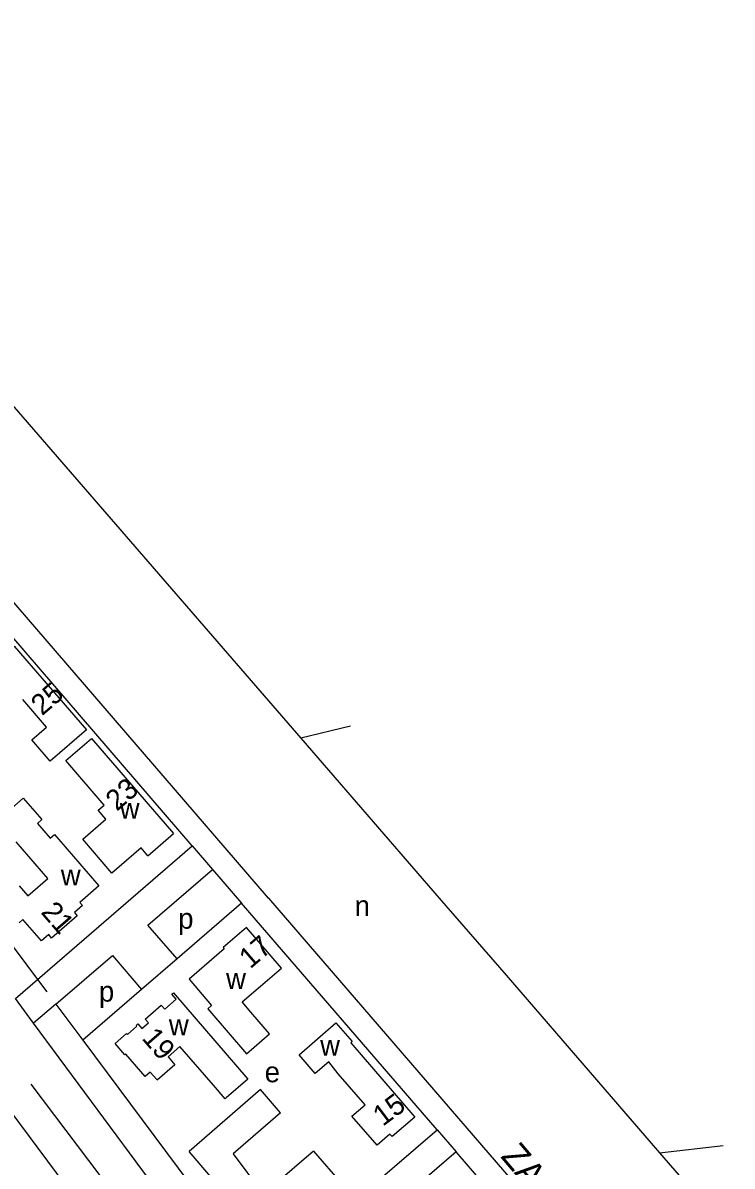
# Model space of a CAD drawing. Extents: x 155854 to 157362, y 383621 to 384685.
# Drawn here: x 156707.1 to 156844.9, y 384447.9 to 384670 of the extents above; entities that cross this region are included whole.
import ezdxf

# ---------------------------------------------------------------- set-up
doc = ezdxf.new("R2010")
doc.units = 0
for name, color, linetype in [('BLT_Basislijn', 7, 'Continuous'), ('BLT_Bebouwing', 7, 'Continuous'), ('BLT_Centroide', 7, 'Continuous'), ('BLT_Huisnummer', 7, 'Continuous'), ('BLT_Straatnaam', 7, 'Continuous'), ('BLT_Vlakafsluiter', 7, 'Continuous')]:
    doc.layers.add(name, color=color, linetype=linetype)

msp = doc.modelspace()

# ---------------------------------------------------------------- linework, layer by layer
at = {"layer": 'BLT_Basislijn'}
for p, q in [((156738.35, 384519.08), (156620.78, 384655.36)), ((156754.81, 384500), (156738.35, 384519.08)), ((156739.97, 384510.11), (156743.89, 384505.55)), ((156731.33, 384494.75), (156743.89, 384505.55)), ((156743.89, 384505.55), (156749.54, 384498.99)), ((156754.83, 384499.98), (156754.81, 384500)), ((156737.03, 384488.17), (156731.33, 384494.75)), ((156713.47, 384479.41), (156724.48, 384488.82)), ((156724.48, 384488.82), (156730.12, 384482.21)), ((156705.61, 384480.46), (156709.91, 384484.17)), ((156709.91, 384484.17), (156711.69, 384481.79)), ((156736.02, 384481.32), (156736.34, 384481.59)), ((156736.34, 384481.59), (156750.81, 384464.84)), ((156713.47, 384479.41), (156709.1, 384475.67)), ((156734.62, 384478.39), (156736.86, 384480.35)), ((156736.86, 384480.35), (156736.02, 384481.32)), ((156709.1, 384475.67), (156707.36, 384478.07)), ((156730.81, 384476.5), (156733.92, 384479.2)), ((156733.92, 384479.2), (156734.62, 384478.39)), ((156727.37, 384473.5), (156729.2, 384475.11)), ((156729.07, 384475.27), (156729.39, 384475.55)), ((156729.2, 384475.11), (156729.07, 384475.27)), ((156729.39, 384475.55), (156730.18, 384474.64)), ((156730.18, 384474.64), (156731.46, 384475.76)), ((156731.46, 384475.76), (156730.81, 384476.5)), ((156724.99, 384471.73), (156727.23, 384473.66)), ((156727.23, 384473.66), (156727.37, 384473.5)), ((156726.89, 384469.51), (156724.99, 384471.73)), ((156737.58, 384471.15), (156735.27, 384469.16)), ((156744.1, 384463.62), (156737.58, 384471.15)), ((156727.09, 384469.65), (156726.89, 384469.51)), ((156730.83, 384465.31), (156727.09, 384469.65)), ((156735.27, 384469.16), (156736.6, 384467.61)), ((156731.83, 384466.19), (156730.83, 384465.31)), ((156733.07, 384464.76), (156731.83, 384466.19)), ((156736.6, 384467.61), (156733.17, 384464.64)), ((156708.63, 384463.84), (156739.93, 384422.47)), ((156733.17, 384464.64), (156733.07, 384464.76)), ((156750.81, 384464.84), (156746.57, 384461.18)), ((156746.35, 384460.99), (156744.1, 384463.62)), ((156746.57, 384461.18), (156746.35, 384460.99)), ((156787.55, 384455), (156791.25, 384450.67))]:
    msp.add_line(p, q, dxfattribs=at)
for points in [[(156640.63, 384670.01), (156709.96, 384590.03), (156761.05, 384531.07)], [(156739.97, 384510.11), (156702.06, 384554.11)], [(156675.02, 384530.89), (156709.91, 384484.17)], [(156761.05, 384531.07), (156787.96, 384500)], [(156709.91, 384484.17), (156739.97, 384510.11)], [(156728.01, 384499.98), (156728.03, 384500)], [(156828.31, 384414.81), (156754.83, 384499.98)], [(156787.96, 384500), (156787.98, 384499.98)], [(156787.98, 384499.98), (156800.96, 384484.99)], [(156749.54, 384498.99), (156737.03, 384488.17)], [(156787.55, 384455), (156749.54, 384498.99)], [(156737.03, 384488.17), (156730.12, 384482.21)], [(156800.96, 384484.99), (156830.82, 384450.53)], [(156730.12, 384482.21), (156718.73, 384472.36)], [(156713.47, 384479.41), (156718.73, 384472.36)], [(156749.05, 384421.85), (156709.1, 384475.67)], [(156726.96, 384411.19), (156730.91, 384406.67), (156732.14, 384407.62), (156733.47, 384408.89), (156734.43, 384410.44), (156734.94, 384411.69), (156735.4, 384413.39), (156735.49, 384414.94), (156735.24, 384416.83), (156734.81, 384418.13), (156704.77, 384458.46), (156695.52, 384470.73)], [(156718.73, 384472.36), (156753.52, 384425.7)], [(156753.52, 384425.7), (156787.55, 384455)], [(156791.25, 384450.67), (156756.91, 384421.13)], [(156824.78, 384411.77), (156791.25, 384450.67)], [(156830.82, 384450.53), (156854.55, 384423.14), (156867.14, 384408.69)]]:
    msp.add_lwpolyline(points, dxfattribs=at)
at = {"layer": 'BLT_Bebouwing'}
for p, q in [((156715.41, 384526.7), (156720.41, 384531.01)), ((156720.41, 384531.01), (156736.35, 384512.53)), ((156697.44, 384510.99), (156707.13, 384519.39)), ((156707.13, 384519.39), (156710.73, 384515.23)), ((156710.73, 384515.23), (156709.9, 384514.51)), ((156709.9, 384514.51), (156712.39, 384511.64)), ((156711.92, 384503.78), (156705.75, 384510.91)), ((156712.39, 384511.64), (156713.22, 384512.35)), ((156713.22, 384512.35), (156721.85, 384502.39)), ((156731.35, 384508.22), (156736.35, 384512.53)), ((156708.04, 384500.42), (156711.92, 384503.78)), ((156706.34, 384502.39), (156708.04, 384500.42)), ((156721.85, 384502.39), (156718.15, 384499.14)), ((156718.64, 384498.58), (156717.07, 384497.19)), ((156717.07, 384497.19), (156717.63, 384496.54)), ((156718.15, 384499.14), (156718.64, 384498.58)), ((156707.06, 384495.81), (156706.31, 384495.18)), ((156710.67, 384491.67), (156707.06, 384495.81)), ((156717.63, 384496.54), (156712.65, 384492.23)), ((156712.08, 384492.89), (156710.67, 384491.67)), ((156712.65, 384492.23), (156712.08, 384492.89)), ((156753.25, 384462.78), (156739.35, 384450.78)), ((156757.14, 384458.27), (156753.25, 384462.78)), ((156757.14, 384458.27), (156747.93, 384450.33)), ((156743.61, 384445.84), (156739.35, 384450.78)), ((156763.54, 384450.85), (156755.71, 384444.1)), ((156763.54, 384450.85), (156769.03, 384444.49)), ((156747.93, 384450.33), (156758.25, 384436.52))]:
    msp.add_line(p, q, dxfattribs=at)
for points in [[(156701.47, 384545.58), (156705.38, 384548.95), (156719.42, 384532.65), (156712.37, 384526.58), (156708.8, 384530.72), (156711.68, 384533.21), (156707.05, 384538.55)], [(156731.35, 384508.22), (156730.04, 384509.74), (156724.36, 384504.84), (156718.68, 384511.42), (156723.18, 384515.31), (156721.69, 384517.04), (156722.86, 384518.06), (156715.41, 384526.7)], [(156753.21, 384482.87), (156757.31, 384486.4), (156750.5, 384494.28), (156745.96, 384490.38), (156746.18, 384490.13), (156739.35, 384484.23)], [(156739.35, 384484.23), (156743.75, 384479.11), (156743.01, 384478.45), (156750.54, 384469.75), (156755.01, 384473.6), (156751.36, 384477.8), (156749.67, 384479.84), (156753.21, 384482.87)]]:
    msp.add_lwpolyline(points, dxfattribs=at)
msp.add_lwpolyline([(156760.73, 384469.56), (156767.88, 384475.73), (156771.04, 384472.1), (156770.79, 384471.89), (156783.22, 384457.45), (156778.82, 384453.65), (156778.38, 384454.15), (156775.89, 384451.99), (156771.02, 384457.63), (156773.59, 384459.8), (156768.32, 384465.84), (156766.55, 384468.21), (156763.88, 384465.9)], close=True, dxfattribs=at)
at = {"layer": 'BLT_Vlakafsluiter'}
for p, q in [((156770.73, 384533.41), (156761.05, 384531.07)), ((156707.36, 384478.07), (156705.61, 384480.46)), ((156830.82, 384450.53), (156843.17, 384451.96))]:
    msp.add_line(p, q, dxfattribs=at)

# ---------------------------------------------------------------- texts
at = {"layer": 'BLT_Centroide'}
for s, p in [('w', (156725.88, 384515.41)), ('w', (156714.43, 384502.45)), ('n', (156771.54, 384496.48)), ('p', (156737.25, 384494.03)), ('w', (156746.55, 384482.36)), ('p', (156721.84, 384479.87)), ('w', (156735.43, 384473.34)), ('w', (156764.83, 384469.38)), ('e', (156754.06, 384464.21))]:
    msp.add_text(s, height=4, dxfattribs=at).set_placement(p)
at = {"layer": 'BLT_Huisnummer'}
for s, rotation, p in [('25', 40.7831, (156710.8, 384535.3)), ('23', 40.7849, (156725.32, 384516.74)), ('21', 310.7849, (156710.41, 384497.17)), ('17', 40.7868, (156751.25, 384486.12)), ('19', 310.7849, (156730.03, 384472.7)), ('15', 36.8172, (156777.01, 384455.54))]:
    msp.add_text(s, height=4, rotation=rotation, dxfattribs=at).set_placement(p)
at = {"layer": 'BLT_Straatnaam'}
msp.add_text('ZANDOEVER', height=5, rotation=310.2609, dxfattribs=at).set_placement((156799.77, 384449.74))

doc.saveas('drawing.dxf')
